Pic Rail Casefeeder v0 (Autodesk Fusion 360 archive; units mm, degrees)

design "Pic Rail Casefeeder" references "Glock tool holder"
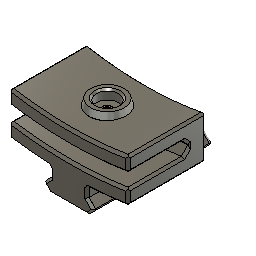
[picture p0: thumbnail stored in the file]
external_derived "ExternalDerived"
sketch "Sketch1" plane through (0, 0, 0) normal (0, 0, 1) x axis (1, 0, 0)
  line L1 (19.6871, -13.589) -> (-21.0466, -13.589)
  line L2 (19.6871, 28.5727) -> (19.6871, -13.589)
  line L3 (-21.0466, 28.5727) -> (19.6871, 28.5727)
  line L4 (-21.0466, -13.589) -> (-21.0466, 28.5727)
  horizontal L1
  perpendicular L1 L2
  perpendicular L2 L3
  perpendicular L1 L4
extrude "Extrude1" cut sketch "Sketch1" blind -183.3118 from offset 12.7
sketch "Sketch2" plane through (-7.747, 0, 0) normal (-1, 0, 0) x axis (0, 0, 1)
  line L1 (-33.241, -22.2215) -> (-28.0848, -22.2215)
  line L2 (-34.8028, -95.8564) -> (-34.8028, -5.84)
  line L3 (-171.6011, -95.8564) -> (-34.8028, -95.8564)
  line L4 (-171.6011, -5.84) -> (-171.6011, -95.8564)
  line L5 (-34.8028, -5.84) -> (-171.6011, -5.84)
  perpendicular L1 L2
  perpendicular L2 L3
  perpendicular L3 L4
  perpendicular L2 L5
extrude "Extrude2" cut sketch "Sketch2" profile of L2 L3 L4 L5 blind -36.4236 from offset 12.7
sketch "Sketch3" plane through (0, -23.3427, 0) normal (0, -1, 0) x axis (1, 0, 0)
  line L1 (10.5414, -33.7749) -> (10.5414, -2.9718)
  line L2 (13.2113, -3.4519) -> (-13.6416, -3.4519)
  line L3 (13.2113, -34.6752) -> (13.2113, -3.4519)
  line L4 (-12.6246, -34.6752) -> (13.2113, -34.6752)
  line L5 (-13.6416, -3.4519) -> (-12.6246, -34.6752)
  line L6 (-13.6416, 6.2993) -> (-13.6416, -3.4519)
  line L7 (13.2113, 6.2993) -> (-13.6416, 6.2993)
  line L8 (13.2113, -3.4519) -> (13.2113, 6.2993)
  perpendicular L1 L2
  perpendicular L2 L3
  perpendicular L3 L4
  perpendicular L2 L6
  perpendicular L6 L7
  perpendicular L2 L8
extrude "Extrude3" cut sketch "Sketch3" profile of L2 L6 L7 L8 against normal blind 15.367
delete_face "DeleteFace1"
delete_face "DeleteFace2"
extrude "Extrude1" new body of existing geometry to an object
delete_face "DeleteFace3"
delete_face "DeleteFace4"
delete_face "DeleteFace5"
delete_face "DeleteFace6"
extrude "Extrude2" new body of existing geometry blind 25.4
sketch "Sketch4" plane through (0, -13.589, 0) normal (0, 1, 0) x axis (0, 0, 1)
  line L1 (-34.8028, -9.4996) -> (-3.4519, -9.4996)
  line L2 (-34.8028, 9.2456) -> (-3.4519, 9.2456)
  line L3 (-6.2204, 9.2456) -> (-6.2204, -9.4996)
  line L4 (-60.2028, 9.2456) -> (-34.8028, 9.2456)
  line L5 (-57.0204, 9.2456) -> (-6.2204, 9.2456)
  line L6 (-60.2028, -9.4996) -> (-34.8028, -9.4996)
  line L7 (-57.0204, -9.4996) -> (-57.0204, 9.2456)
  line L8 (-57.0204, -9.4996) -> (-6.2204, -9.4996)
  line L9 (-57.0204, -13.6255) -> (-57.0204, -9.4996)
  line L10 (-6.2204, -13.6255) -> (-57.0204, -13.6255)
  line L11 (-6.2204, -9.4996) -> (-6.2204, -13.6255)
  line L12 (-6.2204, 12.6645) -> (-6.2204, 9.2456)
  line L13 (-57.0204, 12.6645) -> (-6.2204, 12.6645)
  line L14 (-57.0204, 9.2456) -> (-57.0204, 12.6645)
  line L15 (-63.1409, 12.6645) -> (-57.0204, 12.6645)
  line L16 (-63.1409, -13.6255) -> (-63.1409, 12.6645)
  line L17 (-57.0204, -13.6255) -> (-63.1409, -13.6255)
  line L18 (-1.7561, -13.6255) -> (-6.2204, -13.6255)
  line L19 (-1.7561, 12.6645) -> (-1.7561, -13.6255)
  line L20 (-6.2204, 12.6645) -> (-1.7561, 12.6645)
  point P6 (-6.2204, -9.4996)
  point P7 (-6.2204, 9.2456)
  point P10 (-57.0204, 9.2456)
  point P13 (-57.0204, -9.4996)
  coincident L1 P6
  coincident L2 P7
  perpendicular L2 L3
  coincident L4 P10
  coincident L6 P13
  perpendicular L4 L7
  perpendicular L6 L9
  perpendicular L9 L10
  perpendicular L1 L11
  perpendicular L2 L12
  perpendicular L12 L13
  perpendicular L4 L14
  perpendicular L14 L15
  perpendicular L10 L16
  perpendicular L9 L17
  perpendicular L11 L18
  perpendicular L13 L19
  perpendicular L12 L20
  dimension "d13" distance P7 P10 = 50.8
extrude "Extrude4" cut sketch "Sketch4" profile of L3 L7 L9 L11 L12 L14 L15 L16 L17 L18 L19 L20 to an object
delete_face "DeleteFace7"
delete_face "DeleteFace8"
delete_face "DeleteFace9"
delete_face "DeleteFace10"
sketch "Sketch5" plane through (0, -23.3427, 0) normal (0, -1, 0) x axis (1, 0, 0)
  line L1 (7.7216, -34.8028) -> (7.7216, -6.2204)
  line L2 (8.0268, -32.987) -> (-8.1276, -32.987)
  line L3 (8.0268, -38.3464) -> (-8.1276, -38.3464)
  line L4 (-8.1276, -42.9946) -> (-8.1276, -38.3464)
  line L5 (8.0268, -57.0204) -> (8.0268, -34.8028)
  line L6 (8.0268, -42.9946) -> (-8.1276, -42.9946)
  line L7 (-8.1276, -48.354) -> (-8.1276, -42.9946)
  line L8 (-8.1276, -53.0022) -> (-8.1276, -48.354)
  line L9 (8.0268, -53.0022) -> (-8.1276, -53.0022)
  line L10 (8.0268, -48.354) -> (-8.1276, -48.354)
  line L11 (11.6034, -48.354) -> (8.0268, -48.354)
  line L12 (11.6034, -53.0022) -> (11.6034, -48.354)
  line L13 (8.0268, -53.0022) -> (11.6034, -53.0022)
  line L14 (-12.1861, -53.0022) -> (-8.1276, -53.0022)
  line L15 (-12.1861, -48.354) -> (-12.1861, -53.0022)
  line L16 (-8.1276, -48.354) -> (-12.1861, -48.354)
  line L17 (-13.0161, -42.9946) -> (-8.1276, -42.9946)
  line L18 (-13.0161, -38.3464) -> (-13.0161, -42.9946)
  line L19 (-8.1276, -38.3464) -> (-13.0161, -38.3464)
  line L20 (11.9895, -38.3464) -> (8.0268, -38.3464)
  line L21 (11.9895, -42.9946) -> (11.9895, -38.3464)
  line L22 (8.0268, -42.9946) -> (11.9895, -42.9946)
  point P2 (-8.1276, -32.987)
  point P6 (-8.1276, -32.987)
  point P3 (8.0268, -32.987)
  point P7 (8.0268, -32.987)
  point P13 (8.0268, -42.9946)
  point P16 (8.0268, -53.0022)
  point P17 (8.0268, -48.354)
  point P8 (-8.1276, -38.3464)
  point P10 (-8.1276, -42.9946)
  point P14 (-8.1276, -48.354)
  point P15 (-8.1276, -53.0022)
  coincident P2 P6
  coincident P3 P7
  perpendicular L3 L4
  coincident L5 P13
  perpendicular L4 L6
  perpendicular L6 L7
  parallel L7 L8
  coincident L5 P16
  perpendicular L5 L9
  coincident L5 P17
  perpendicular L5 L10
  perpendicular L5 L11
  perpendicular L9 L12
  perpendicular L5 L13
  perpendicular L8 L14
  perpendicular L10 L15
  perpendicular L7 L16
  perpendicular L7 L17
  perpendicular L3 L18
  perpendicular L4 L19
  perpendicular L5 L20
  perpendicular L6 L21
  perpendicular L5 L22
  dimension "d18" = 5.3594
  dimension "d19" distance P8 P10 = 4.6482
  dimension "d20" distance P10 P14 = 5.3594
  dimension "d21" distance P14 P15 = 4.6482
extrude "Extrude4" cut sketch "Sketch5" profile of L3 L4 L5 L6 L8 L9 L10 L11 L12 L13 L14 L15 L16 L17 L18 L19 L20 L21 L22 to an object
extrude "Extrude5" add of existing geometry blind 0.9525
extrude "Extrude6" cut of existing geometry blind -0.9525
sketch "Sketch6" plane through (0, 0, -5.2679) normal (0, 0, 1) x axis (1, 0, 0)
  line L1 (-7.9756, -13.2961) -> (-7.9756, -15.113)
  line L2 (-9.9762, -13.2961) -> (-7.9756, -13.2961)
  line L3 (-7.9756, -15.113) -> (-9.9762, -13.2961)
  line L4 (-9.4996, -13.589) -> (9.2456, -13.589)
  line L5 (7.7216, -13.2961) -> (7.7216, -15.113)
  line L6 (9.8346, -13.2961) -> (7.7216, -13.2961)
  line L7 (7.7216, -15.113) -> (9.8346, -13.2961)
  arc A1 centre (-9.4996, -15.113) radius 1.524 clockwise from (-9.4996, -13.589) to (-7.9756, -15.113)
  point P2 (-7.9756, -15.113)
  point P6 (-7.9756, -15.113)
  point P9 (-7.9756, -15.113)
  point P10 (-7.9756, -15.113)
  point P11 (7.7216, -15.113)
  point P14 (7.7216, -15.113)
  point P17 (7.7216, -15.113)
  point P18 (7.7216, -15.113)
  coincident P2 P6
  tangent A1 L1
  vertical L1
  perpendicular L1 L2
  coincident P9 P10
  coincident P11 P14
  perpendicular L4 L5
  perpendicular L5 L6
  coincident P17 P18
extrude "Extrude5" cut sketch "Sketch6" to an object
sketch "Sketch7" plane through (0, 0, -56.0679) normal (0, 0, -1) x axis (-1, 0, 0)
  line L1 (-7.7216, -13.589) -> (7.9756, -13.589)
  line L2 (7.9756, -13.589) -> (-7.7216, -13.589)
  line L3 (0.127, 5.334) -> (0.127, -13.589)
  line L4 (3.429, 5.334) -> (3.429, -13.589)
  line L5 (-3.175, 5.7663) -> (-3.175, -13.589)
  line L6 (-13.4313, 18.0107) -> (-17.5962, 18.0107)
  line L7 (17.8616, 18.161) -> (14.1667, 18.161)
  line L8 (12.827, -13.589) -> (3.429, -13.589)
  line L9 (-12.573, -0.889) -> (-12.573, -9.779)
  line L10 (12.827, -0.889) -> (12.827, -9.779)
  line L11 (0.127, -13.589) -> (9.017, -13.589)
  line L12 (-8.763, -13.589) -> (-3.175, -13.589)
  arc A1 centre (0.127, 18.161) radius 12.827 clockwise from (12.9018, 17.0054) to (-12.6711, 17.2999)
  arc A2 centre (0.127, 18.161) radius 19.05 clockwise from (-15.113, 6.731) to (-18.8621, 16.6393)
  arc A3 centre (0.127, 18.161) radius 19.05 clockwise from (19.1283, 16.8003) to (15.367, 6.731)
  arc A4 centre (-17.5962, 16.7407) radius 1.27 clockwise from (-18.8621, 16.6393) to (-17.5962, 18.0107)
  arc A5 centre (-13.4313, 17.2487) radius 0.762 clockwise from (-13.4313, 18.0107) to (-12.6711, 17.2999)
  arc A6 centre (14.1667, 16.891) radius 1.27 clockwise from (12.9018, 17.0054) to (14.1667, 18.161)
  arc A7 centre (17.8616, 16.891) radius 1.27 clockwise from (17.8616, 18.161) to (19.1283, 16.8003)
  arc A8 centre (-25.273, -0.889) radius 12.7 clockwise from (-15.113, 6.731) to (-12.573, -0.889)
  arc A9 centre (25.527, -0.889) radius 12.7 clockwise from (12.827, -0.889) to (15.367, 6.731)
  arc A10 centre (-8.763, -9.779) radius 3.81 clockwise from (-8.763, -13.589) to (-12.573, -9.779)
  arc A11 centre (9.017, -9.779) radius 3.81 clockwise from (12.827, -9.779) to (9.017, -13.589)
  point P6 (0.127, -13.589)
  point P12 (-3.175, 5.7663)
  point P13 (0.127, 5.334)
  point P28 (-12.573, -13.589)
  point P27 (12.827, -13.589)
  point P7 (0.127, 18.161)
  midpoint L1 P6
  perpendicular L2 L3
  concentric A1 A2
  horizontal L6
  perpendicular L4 L7
  parallel L3 L5
  coincident A1 P12
  coincident A1 P13
  tangent L6 A4
  tangent A2 A4
  tangent L6 A5
  tangent A1 A5
  tangent L7 A6
  tangent A1 A6
  tangent L7 A7
  tangent A3 A7
  perpendicular L3 L8
  perpendicular L9 L11
  perpendicular L8 L10
  collinear L11 L12
  tangent L9 A8
  tangent A2 A8
  tangent L10 A9
  tangent A3 A9
  coincident P28 L9
  coincident P28 L12
  tangent L9 A10
  tangent L12 A10
  coincident P27 L11
  coincident P27 L10
  tangent L11 A11
  tangent L10 A11
  dimension "d32" distance P6 P7 = 31.75
  dimension "d33" diameter A1 = 25.654
  dimension "d34" diameter A2 = 38.1
  dimension "d35" = 3.302
  dimension "d39" radius A4 = 1.27
  dimension "d40" radius A5 = 0.762
  dimension "d41" radius A6 = 1.27
  dimension "d42" radius A7 = 1.27
  dimension "d47" distance P6 P27 = 12.7
  dimension "d48" distance P27 P28 = 25.4
  dimension "d49" radius A8 = 12.7
  dimension "d50" radius A9 = 12.7
  dimension "d51" radius A10 = 3.81
  dimension "d52" radius A11 = 3.81
extrude "Extrude9" add sketch "Sketch7" profile of L1 L2 L3 A1 A3 L5 L6 L7 A4 A5 A6 A7 L8 L12 L9 L10 A8 A9 A10 A11 to an object
extrude "Extrude8" add sketch "Sketch7" profile of L1 L2 L3 A1 A3 L5 L6 L7 A4 A5 A6 A7 to an object
sketch "Sketch9" plane through (12.573, 0, 0) normal (1, 0, 0) x axis (0, 0, -1)
  line L1 (5.2679, -9.779) -> (56.0679, -9.779)
  line L2 (5.2679, 18.161) -> (56.0679, 18.161)
  line L3 (30.6679, 20.657) -> (30.6679, -9.779)
  line L4 (14.7929, 20.657) -> (14.7929, 18.161)
  line L5 (-2.5282, -9.779) -> (14.7929, -9.779)
  line L6 (-2.5282, 21.9055) -> (-2.5282, -9.779)
  line L7 (30.6679, 21.9055) -> (-2.5282, 21.9055)
  line L8 (30.6679, 20.657) -> (30.6679, 21.9055)
  arc A1 centre (14.7929, 6.096) radius 15.8886 clockwise from (30.6679, 6.753) to (14.1359, -9.779)
  point P6 (30.6679, -9.779)
  point P14 (30.6679, 6.753)
  point P15 (14.1359, -9.779)
  point P16 (14.7929, 18.161)
  point P8 (14.7929, -9.779)
  point P10 (14.7929, 6.096)
  midpoint L1 P6
  perpendicular L2 L3
  perpendicular L5 L6
  perpendicular L6 L7
  perpendicular L7 L8
  coincident L3 P14
  coincident L1 P15
  parallel L3 L4
  coincident L2 P16
  dimension "d59" distance P8 P10 = 15.875
extrude "Extrude11" cut sketch "Sketch9" profile of L1 L3 A1 L5 L6 L7 L8 blind -47.752 from offset 12.7
sketch "Sketch10" plane through (0, 0, -56.0679) normal (0, 0, -1) x axis (-1, 0, 0)
  line L1 (-0.0207, -5.3331) -> (-0.0207, 5.3349)
  line L2 (5.8213, -5.3331) -> (-0.0207, -5.3331)
  line L3 (-0.0207, -5.3331) -> (5.8213, -5.3331)
  line L4 (-5.8627, -5.3331) -> (-0.0207, -5.3331)
  line L5 (-5.8627, -0.7611) -> (-5.8627, -5.3331)
  line L6 (5.8213, -0.7611) -> (5.8213, -5.3331)
  line L7 (-3.3227, -0.7611) -> (-3.3227, 5.8066)
  line L8 (3.2813, -0.7611) -> (3.2813, 5.7279)
  line L9 (-3.3227, -0.7611) -> (-5.8627, -0.7611)
  line L10 (3.2813, -0.7611) -> (5.8213, -0.7611)
  line L11 (-3.3227, 6.7705) -> (-3.3227, 5.8066)
  line L12 (3.2813, 6.7705) -> (-3.3227, 6.7705)
  line L13 (3.2813, 5.7279) -> (3.2813, 6.7705)
  arc A1 centre (0.127, 18.161) radius 12.827 clockwise from (12.9018, 17.0054) to (-12.6711, 17.2999)
  point P5 (-0.0207, 5.3349)
  point P13 (-3.3227, 5.8066)
  point P14 (3.2813, 5.7279)
  point P6 (-0.0207, -5.3331)
  point P8 (-5.8627, -5.3331)
  midpoint A1 P5
  vertical L1
  perpendicular L1 L2
  perpendicular L1 L4
  perpendicular L4 L5
  perpendicular L2 L6
  perpendicular L7 L9
  perpendicular L8 L10
  parallel L1 L7
  coincident A1 P13
  parallel L1 L8
  coincident A1 P14
  parallel L7 L11
  perpendicular L8 L12
  dimension "d65" distance P6 P8 = 5.842
extrude "Extrude12" cut sketch "Sketch10" against normal blind 18.288
sketch "Sketch11" plane through (0, -5.3331, 0) normal (0, 1, 0) x axis (-1, 0, 0)
  line L1 (-5.8627, -56.0679) -> (5.8213, -56.0679)
  line L2 (-8.0268, -56.0679) -> (8.1276, -56.0679)
  line L3 (0.0504, -56.0679) -> (-0.0207, -56.0679)
  line L4 (-3.3227, -37.7799) -> (-3.3227, -56.0679)
  line L5 (-5.8627, -37.7799) -> (5.8213, -37.7799)
  line L6 (3.2813, -37.7799) -> (3.2813, -43.3679)
  line L7 (3.2813, -37.7799) -> (-3.3227, -37.7799)
  line L8 (-3.3227, -43.3679) -> (-3.3227, -37.7799)
  arc A1 centre (-0.0207, -43.3679) radius 3.302 clockwise from (-3.3227, -43.3679) to (3.2813, -43.3679)
  point P6 (-0.0207, -56.0679)
  point P7 (0.0504, -56.0679)
  point P11 (3.2813, -37.7799)
  point P15 (3.2813, -37.7799)
  point P10 (-3.3227, -37.7799)
  point P16 (-3.3227, -37.7799)
  point P17 (3.2813, -37.7799)
  point P18 (-3.3227, -43.3679)
  point P8 (-0.0207, -43.3679)
  midpoint L1 P6
  midpoint L2 P7
  tangent L4 A1
  coincident P11 P15
  perpendicular L5 L6
  coincident P10 P16
  coincident P11 P17
  coincident L4 P18
  dimension "d72" distance P6 P8 = 12.7
extrude "Extrude13" add sketch "Sketch11" profile of A1 L4 L5 L6 L7 L8 blind 7.9756 from offset 4.572
sketch "Sketch12" plane through (0, 0, -37.7799) normal (0, 0, 1) x axis (1, 0, 0)
  line L1 (-3.2813, 7.2145) -> (-3.2813, 5.7279)
  line L2 (-3.2813, 7.2145) -> (-3.2813, 5.7279)
  line L3 (-3.2813, 7.2145) -> (3.3227, 7.2145)
  line L4 (3.3227, 5.8066) -> (3.3227, 7.2145)
  arc A1 centre (-0.127, 18.161) radius 12.827 clockwise from (3.3227, 5.8066) to (-3.2813, 5.7279)
  point P2 (-3.2813, 5.7279)
  point P6 (-3.2813, 5.7279)
  point P3 (-3.2813, 7.2145)
  point P7 (-3.2813, 7.2145)
  point P8 (3.3227, 7.2145)
  point P9 (3.3227, 7.2145)
  point P10 (-3.2813, 7.2145)
  point P11 (3.3227, 5.8066)
  point P12 (3.3227, 5.8066)
  point P13 (-3.2813, 5.7279)
  coincident P2 P6
  coincident P3 P7
  coincident P8 P9
  coincident P3 P10
  coincident P11 P12
  coincident P2 P13
extrude "Extrude14" cut sketch "Sketch12" against normal blind 6.5278
sketch "Sketch13" plane through (0, -9.779, 0) normal (0, 1, 0) x axis (0, 0, 1)
  line L1 (-15.4499, 15.6111) -> (-15.4499, 12.573)
  line L2 (-3.1431, 15.6111) -> (-15.4499, 15.6111)
  line L3 (-3.1431, 7.5536) -> (-3.1431, 15.6111)
  line L4 (-3.1431, 7.7216) -> (-5.2679, 7.7216)
  line L5 (-5.2679, -12.827) -> (-5.2679, 12.573)
  line L6 (-3.1431, -7.9756) -> (-5.2679, -7.9756)
  line L7 (-3.1431, -15.2405) -> (-3.1431, -7.9756)
  line L8 (-15.4499, -15.2405) -> (-3.1431, -15.2405)
  line L9 (-15.4499, -15.2405) -> (-15.4499, -12.827)
  line L10 (-6.5379, -7.9756) -> (-5.2679, -7.9756)
  line L11 (-6.5379, -7.9756) -> (-15.4499, -12.827)
  line L12 (-6.5379, 7.7216) -> (-5.2679, 7.7216)
  line L13 (-15.4499, 12.573) -> (-6.5379, 7.7216)
  point P4 (-5.2679, -7.9756)
  point P6 (-5.2679, -7.9756)
  point P3 (-5.2679, 7.7216)
  point P8 (-5.2679, 7.7216)
  point P7 (-15.4499, 12.573)
  point P9 (-15.4499, 12.573)
  point P13 (-3.1431, 7.7216)
  point P16 (-5.2679, -7.9756)
  point P5 (-15.4499, -12.827)
  point P20 (-15.4499, -12.827)
  point P22 (-15.4499, -12.827)
  point P23 (-5.2679, 7.7216)
  point P25 (-15.4499, 12.573)
  point P21 (-6.5379, -7.9756)
  point P24 (-6.5379, 7.7216)
  coincident P4 P6
  coincident P3 P8
  coincident P7 P9
  perpendicular L1 L2
  perpendicular L2 L3
  coincident L3 P13
  perpendicular L3 L4
  coincident P4 P16
  perpendicular L5 L6
  perpendicular L4 L7
  perpendicular L7 L8
  coincident P5 P20
  perpendicular L8 L9
  parallel L6 L10
  coincident P5 P22
  coincident P3 P23
  perpendicular L5 L12
  coincident P7 P25
  dimension "d80" distance P6 P21 = 1.27
  dimension "d81" distance P23 P24 = 1.27
extrude "Extrude15" cut sketch "Sketch13" profile of L1 L2 L3 L4 L6 L7 L8 L9 against normal blind 6.6802
chamfer "Chamfer1" distance 0.9144
fillet "Fillet1" radius 1.27 1.27
chamfer "Chamfer2" distance 0.6858
fillet "Fillet2" radius 1.27 1.27 1.27 1.27 1.27
chamfer "Chamfer3" distance 0.508
sketch "Sketch1" plane through (0, 0, -56.0679) normal (0, 0, -1) x axis (-1, 0, 0)
  line L1 (6.7056, -18.1288) -> (6.7056, -12.319)
  line L2 (7.9756, -13.589) -> (-7.7216, -13.589)
  line L3 (32.4769, -13.589) -> (7.9756, -13.589)
  line L4 (-32.1952, -13.589) -> (32.4769, -13.589)
  line L5 (-32.1952, 30.0805) -> (-32.1952, -13.589)
  line L6 (20.2262, 30.0805) -> (-32.1952, 30.0805)
  line L7 (20.2262, -13.589) -> (20.2262, 30.0805)
  point P2 (-7.7216, -13.589)
  point P6 (-7.7216, -13.589)
  point P3 (7.9756, -13.589)
  point P7 (7.9756, -13.589)
  point P12 (20.2262, -13.589)
  coincident P2 P6
  coincident P3 P7
  perpendicular L1 L3
  perpendicular L1 L4
  perpendicular L4 L5
  perpendicular L5 L6
  midpoint L3 P12
  perpendicular L3 L7
extrude "Extrude16" cut sketch "Sketch1" profile of L2 L3 L4 L5 L6 L7 to an object
sketch "Sketch2" plane through (0, 0, -5.2679) normal (0, 0, 1) x axis (1, 0, 0)
  line L1 (7.7216, -13.589) -> (-7.9756, -13.589)
  line L2 (6.8072, -13.589) -> (-7.0612, -13.589)
  line L3 (-7.9756, -13.4023) -> (-7.9756, -13.589)
  line L4 (7.7216, -13.4023) -> (7.7216, -13.589)
  line L5 (25.273, 3.8192) -> (25.273, -11.6235)
  line L6 (-25.527, 3.8192) -> (-25.527, -11.6235)
  line L7 (-25.527, 6.9834) -> (-25.527, 0.5986)
  line L8 (25.273, 6.9834) -> (25.273, 0.5986)
  arc A1 centre (-0.127, 151.511) radius 165.1 clockwise from (25.273, -11.6235) to (7.7216, -13.4023)
  arc A2 centre (-0.127, 151.511) radius 165.1 clockwise from (-7.9756, -13.4023) to (-25.527, -11.6235)
  arc A3 centre (-0.127, 151.511) radius 158.75 clockwise from (25.273, -5.1938) to (-25.527, -5.1938)
  arc A4 centre (-0.127, 151.511) radius 153.035 clockwise from (25.273, 0.5986) to (-25.527, 0.5986)
  arc A5 centre (-0.127, 151.511) radius 146.7426 clockwise from (25.273, 6.9834) to (-25.527, 6.9834)
  point P2 (-7.0612, -13.589)
  point P6 (-7.0612, -13.589)
  point P3 (6.8072, -13.589)
  point P7 (6.8072, -13.589)
  point P4 (-7.9756, -13.589)
  point P11 (-7.9756, -13.589)
  point P5 (7.7216, -13.589)
  point P13 (7.7216, -13.589)
  point P17 (-25.527, -11.6235)
  point P20 (25.273, -5.1938)
  point P21 (-25.527, -5.1938)
  point P22 (25.273, 0.5986)
  point P23 (-25.527, 0.5986)
  coincident P2 P6
  coincident P3 P7
  concentric A1 A3
  tangent L1 A1
  coincident P4 P11
  perpendicular L1 L3
  coincident P5 P13
  perpendicular L1 L4
  coincident P17 A1
  concentric A1 A2
  coincident L5 P20
  coincident L6 P21
  coincident L5 P22
  coincident L6 P23
  parallel L6 L7
  parallel L5 L8
extrude "Extrude17" add sketch "Sketch2" profile of L1 L2 A3 A4 A2 L3 L4 L5 L6 to an object
delete_face "DeleteFace1"
delete_face "DeleteFace2"
sketch "Sketch3" plane through (0, -22.5807, 0) normal (0, -1, 0) x axis (1, 0, 0)
  circle C1 centre (-25.527, -56.0679) radius 17.5514
  circle C2 centre (25.273, -56.0679) radius 17.5514
  point P7 (-25.527, -56.0679)
  point P9 (-25.527, -56.0679)
  point P6 (-7.9756, -56.0679)
  point P8 (25.273, -56.0679)
  point P10 (25.273, -56.0679)
  point P5 (7.7216, -56.0679)
  coincident P7 P9
  coincident P6 C1
  coincident P8 P10
  coincident P5 C2
extrude "Extrude18" cut sketch "Sketch3" blind -39.3192 from offset -7.62
extrude "Extrude19" cut sketch "Sketch2" profile of A3 A4 L5 L6 against normal blind 26.67
sketch "Sketch4" plane through (-25.527, 0, 0) normal (-1, 0, 0) x axis (0, 0, 1)
  line L1 (-56.0679, 4.7684) -> (-56.0679, 4.9784)
  circle C1 centre (-56.0679, 4.7684) radius 17.6906
  point P3 (-56.0679, 4.7684)
  point P4 (-56.0679, 4.7684)
  point P5 (-38.5165, 6.9834)
  coincident P3 P4
  coincident C1 P5
extrude "Extrude20" cut sketch "Sketch4" profile of C1 against normal blind 59.8932
fillet "Fillet3" radius 2.54
delete_face "DeleteFace3"
chamfer "Chamfer4" distance 1.016
chamfer "Chamfer5" distance 2.8448
chamfer "Chamfer6" distance 1.016
chamfer "Chamfer7" distance 0.762
chamfer "Chamfer8" distance 1.016
chamfer "Chamfer9" distance 1.016
chamfer "Chamfer10" distance 1.016
fillet "Fillet4" radius 1.27 1.27
sketch "Sketch5" plane through (0, 0, 0) normal (0, 1, 0) x axis (1, 0, 0)
  line L1 (-8.1276, 23.4874) -> (8.0268, 23.4874)
  line L2 (-8.1276, 27.8308) -> (-8.1276, 23.4874)
  line L3 (8.0268, 27.8308) -> (-8.1276, 27.8308)
  line L4 (8.0268, 23.4874) -> (8.0268, 27.8308)
  line L5 (-24.5257, 6.2839) -> (-24.5257, 37.4794)
  line L6 (24.2717, 6.2839) -> (-24.5257, 6.2839)
  line L7 (24.2717, 37.4794) -> (24.2717, 6.2839)
  line L8 (-24.5257, 37.4794) -> (24.2717, 37.4794)
  line L9 (24.2717, 21.8817) -> (-24.5257, 21.8817)
  line L10 (-0.127, 6.2839) -> (-0.127, 37.4794)
  circle C1 centre (-0.127, 21.8817) radius 7.9375
  point P9 (-24.5257, 37.4794)
  point P10 (-24.5257, 37.4794)
  point P8 (-24.5257, 6.2839)
  point P11 (-24.5257, 6.2839)
  point P6 (24.2717, 6.2839)
  point P12 (24.2717, 6.2839)
  point P7 (24.2717, 37.4794)
  point P13 (24.2717, 37.4794)
  point P14 (-24.5257, 37.4794)
  point P15 (-24.5257, 21.8817)
  point P16 (24.2717, 21.8817)
  point P17 (-0.127, 37.4794)
  point P18 (-0.127, 6.2839)
  point P19 (-0.127, 21.8817)
  coincident P9 P10
  coincident P8 P11
  coincident P6 P12
  coincident P7 P13
  coincident P9 P14
  midpoint L5 P15
  midpoint L7 P16
  midpoint L8 P17
  midpoint L6 P18
  midpoint L9 P19
  dimension "d124" diameter C1 = 15.875
extrude "Extrude21" add sketch "Sketch5" profile of L1 L3 L9 L10 C1 along normal blind 7.62
sketch "Sketch6" plane through (0, 7.62, 0) normal (0, 1, 0) x axis (-1, 0, 0)
  line L1 (-8.2808, -18.3312) -> (8.3816, -18.3312)
  line L2 (0.127, -13.9442) -> (0.127, -29.8192)
  line L3 (-7.8105, -21.8817) -> (8.0645, -21.8817)
  circle C1 centre (0.127, -21.8817) radius 7.9375
  point P5 (0.127, -29.8192)
  point P6 (0.127, -13.9442)
  point P7 (8.0645, -21.8817)
  point P9 (8.0645, -21.8817)
  point P8 (-7.8105, -21.8817)
  point P10 (-7.8105, -21.8817)
  coincident C1 P5
  coincident P5
  coincident C1 P6
  coincident P6
  coincident P7 P9
  coincident P8 P10
chamfer "Chamfer11" distance 0.762 distance 2.7686
sketch "Sketch7" plane through (0, 7.62, 0) normal (0, 1, 0) x axis (-1, 0, 0)
  circle C1 centre (0.127, -21.8817) radius 7.1755
extrude "Extrude22" add sketch "Sketch7" to an object
hole "Hole2" HoleDepth 11.557 HoleDiameter 4.064 TipAngle 118 CBDepth 4.064 CBDiameter 9.525
chamfer "Chamfer12" distance 0.7366
sketch "Sketch8" plane through (0, 3.556, 0) normal (0, 1, 0) x axis (-1, 0, 0)
  circle C1 centre (0.127, -21.8817) radius 2.032
  circle C2 centre (0.127, -21.8817) radius 2.032
  point P3 (0.127, -23.9137)
  tangent C1 C2
  coincident C1 P3
extrude "Extrude23" sketch "Sketch8" blind -4.826
hole "Hole3" HoleDepth 7.62 HoleDiameter 3.429 TipAngle 118
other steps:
derived_base_feature "Derived Base Feature" bodies "Body23"
chamfer "Chamfer1" distance 0.508
extrude "Extrude3" cut sketch "Sketch4" profile of L3 L7 L9 L11 L12 L14 L15 L16 L17 L18 L19 L20 to an object
extrude "Extrude7" cut sketch "Sketch6" to an object
thread "Thread2"
create_component "CreateComponent1"
named bodies: "Body23"

design "Glock tool holder"
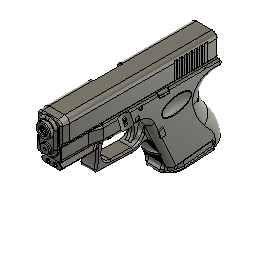
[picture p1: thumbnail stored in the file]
